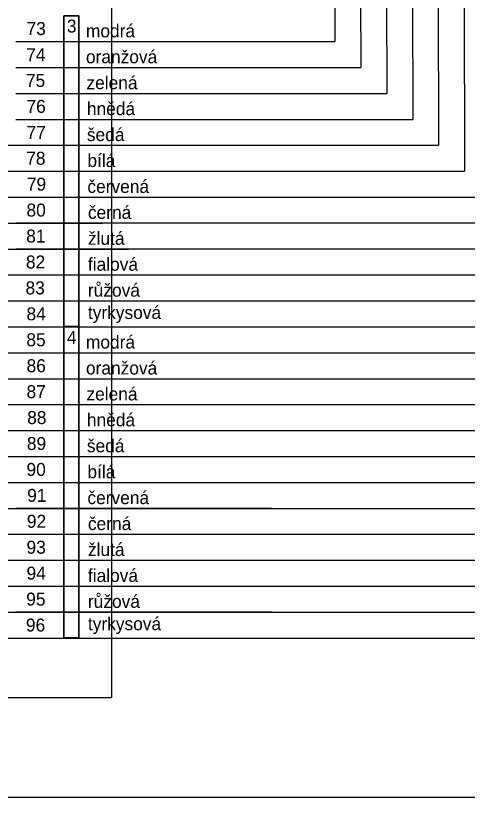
# Model space of a CAD drawing. Extents: x 1901 to 2519, y -3585 to -3154.
# Drawn here: x 2115.5 to 2176.8, y -3585 to -3478.9 of the extents above; entities that cross this region are included whole.
import ezdxf

# ---------------------------------------------------------------- set-up
doc = ezdxf.new("R2010")
doc.units = 0
doc.layers.add('rozvláknění', color=7, linetype='Continuous')
doc.layers.add('Vrstva 4', color=7, linetype='Continuous')

msp = doc.modelspace()

# ---------------------------------------------------------------- linework, layer by layer
at = {"layer": 'rozvláknění'}
for p, q in [((2158.57, -3397.9), (2158.82, -3482.38)), ((2162.09, -3401.42), (2162.34, -3485.9)), ((2165.61, -3404.94), (2165.86, -3489.42)), ((2169.13, -3408.46), (2169.38, -3492.94)), ((2172.65, -3411.98), (2172.9, -3496.46)), ((2176.17, -3415.5), (2176.42, -3499.98)), ((2115.49, -3482.38), (2158.82, -3482.38)), ((2115.49, -3485.9), (2162.34, -3485.9)), ((2115.49, -3489.42), (2165.86, -3489.42)), ((2115.49, -3492.94), (2169.38, -3492.94)), ((2067.76, -3496.46), (2116.69, -3496.46)), ((2115.49, -3496.46), (2172.9, -3496.46)), ((2067.76, -3499.98), (2120.21, -3499.98)), ((2115.49, -3499.97), (2176.42, -3499.97)), ((2067.76, -3503.5), (2123.73, -3503.5)), ((2115.49, -3503.49), (2179.94, -3503.49)), ((2067.76, -3507.02), (2127.25, -3507.02)), ((2115.49, -3507.01), (2183.46, -3507.01)), ((2067.76, -3510.54), (2130.77, -3510.54)), ((2115.49, -3510.53), (2186.98, -3510.53)), ((2067.76, -3514.06), (2134.29, -3514.06)), ((2115.49, -3514.05), (2190.5, -3514.05)), ((2067.76, -3517.58), (2137.81, -3517.58)), ((2115.49, -3517.56), (2194.02, -3517.56)), ((2067.76, -3521.1), (2141.33, -3521.1)), ((2115.49, -3521.1), (2197.54, -3521.1)), ((2067.76, -3524.62), (2144.85, -3524.62)), ((2115.49, -3524.62), (2201.06, -3524.62)), ((2067.76, -3528.14), (2148.37, -3528.14)), ((2115.49, -3528.14), (2204.58, -3528.14)), ((2067.76, -3531.66), (2151.89, -3531.66)), ((2115.49, -3531.66), (2208.1, -3531.66)), ((2067.76, -3535.18), (2155.41, -3535.18)), ((2115.49, -3535.18), (2211.62, -3535.18)), ((2067.76, -3538.7), (2215.14, -3538.7)), ((2115.49, -3538.7), (2150.2, -3538.7)), ((2067.76, -3542.22), (2218.66, -3542.22)), ((2115.49, -3542.21), (2150.2, -3542.21)), ((2067.76, -3545.74), (2222.18, -3545.74)), ((2115.49, -3545.73), (2150.2, -3545.73)), ((2067.76, -3549.26), (2225.7, -3549.26)), ((2115.49, -3549.25), (2150.2, -3549.25)), ((2067.76, -3552.78), (2229.22, -3552.78)), ((2115.49, -3552.77), (2150.2, -3552.77)), ((2067.76, -3556.3), (2232.74, -3556.3)), ((2115.49, -3556.29), (2150.2, -3556.29)), ((2067.76, -3559.82), (2236.26, -3559.82)), ((2115.49, -3559.8), (2150.2, -3559.8)), ((2067.76, -3563.34), (2239.78, -3563.34)), ((2115.49, -3563.34), (2150.2, -3563.34))]:
    msp.add_line(p, q, dxfattribs=at)
for points in [[(2094.46, -3178.54), (2128.46, -3178.54), (2128.46, -3571.47), (2094.46, -3571.47)], [(2124.06, -3563.34), (2122.02, -3563.34), (2122.02, -3478.87), (2124.06, -3478.87)], [(2124.06, -3521.08), (2122.02, -3521.08), (2122.02, -3478.87), (2124.06, -3478.87)], [(2124.06, -3563.32), (2122.02, -3563.32), (2122.02, -3521.11), (2124.06, -3521.11)]]:
    msp.add_lwpolyline(points, close=True, dxfattribs=at)
for points in [[(2124.06, -3478.87), (2122.02, -3478.87), (2122.02, -3521.08), (2124.06, -3521.08), (2124.06, -3478.87)], [(2124.06, -3521.11), (2122.02, -3521.11), (2122.02, -3563.32), (2124.06, -3563.32), (2124.06, -3521.11)]]:
    msp.add_lwpolyline(points, dxfattribs=at)
at = {"layer": 'Vrstva 4'}
msp.add_lwpolyline([(1901.22, -3154.47), (2516.22, -3154.47), (2516.22, -3584.97), (1901.22, -3584.97)], close=True, dxfattribs=at)

# ---------------------------------------------------------------- texts
at = {"layer": 'rozvláknění'}
for s, p in [('73', (2116.94, -3481.5)), ('3', (2122.42, -3481.16)), ('3', (2122.42, -3481.16)), ('modrá', (2125.01, -3481.81)), ('74', (2116.9, -3485.05)), ('oranžová', (2125.01, -3485.33)), ('75', (2116.86, -3488.54)), ('zelená', (2125.08, -3488.85)), ('76', (2116.94, -3492.06)), ('hnědá', (2125.14, -3492.37)), ('77', (2116.94, -3495.61)), ('šedá', (2125.14, -3495.89)), ('78', (2116.9, -3499.1)), ('bílá', (2125.21, -3499.41)), ('79', (2116.99, -3502.62)), ('červená', (2125.21, -3502.93)), ('80', (2116.94, -3506.14)), ('černá', (2125.28, -3506.45)), ('81', (2116.9, -3509.66)), ('žlutá', (2125.28, -3509.97)), ('82', (2116.86, -3513.18)), ('fialová', (2125.28, -3513.49)), ('83', (2116.81, -3516.7)), ('růžová', (2125.28, -3517.01)), ('tyrkysová', (2125.28, -3520.04)), ('84', (2116.94, -3520.22)), ('85', (2116.92, -3523.74)), ('4', (2122.42, -3523.43)), ('4', (2122.42, -3523.43)), ('modrá', (2125.01, -3524.05)), ('86', (2116.95, -3527.26)), ('oranžová', (2125.01, -3527.57)), ('87', (2116.94, -3530.78)), ('zelená', (2125.08, -3531.09)), ('88', (2117.03, -3534.3)), ('hnědá', (2125.14, -3534.61)), ('89', (2116.99, -3537.82)), ('šedá', (2125.14, -3538.13)), ('90', (2116.94, -3541.34)), ('bílá', (2125.21, -3541.65)), ('91', (2117.03, -3544.86)), ('červená', (2125.21, -3545.17)), ('92', (2116.99, -3548.38)), ('černá', (2125.28, -3548.69)), ('93', (2116.94, -3551.9)), ('žlutá', (2125.28, -3552.21)), ('94', (2116.94, -3555.42)), ('fialová', (2125.28, -3555.73)), ('95', (2116.9, -3558.94)), ('růžová', (2125.28, -3559.25)), ('96', (2116.86, -3562.46)), ('tyrkysová', (2125.28, -3562.28))]:
    msp.add_text(s, height=1.76, dxfattribs=at).set_placement(p)

doc.saveas('drawing.dxf')
